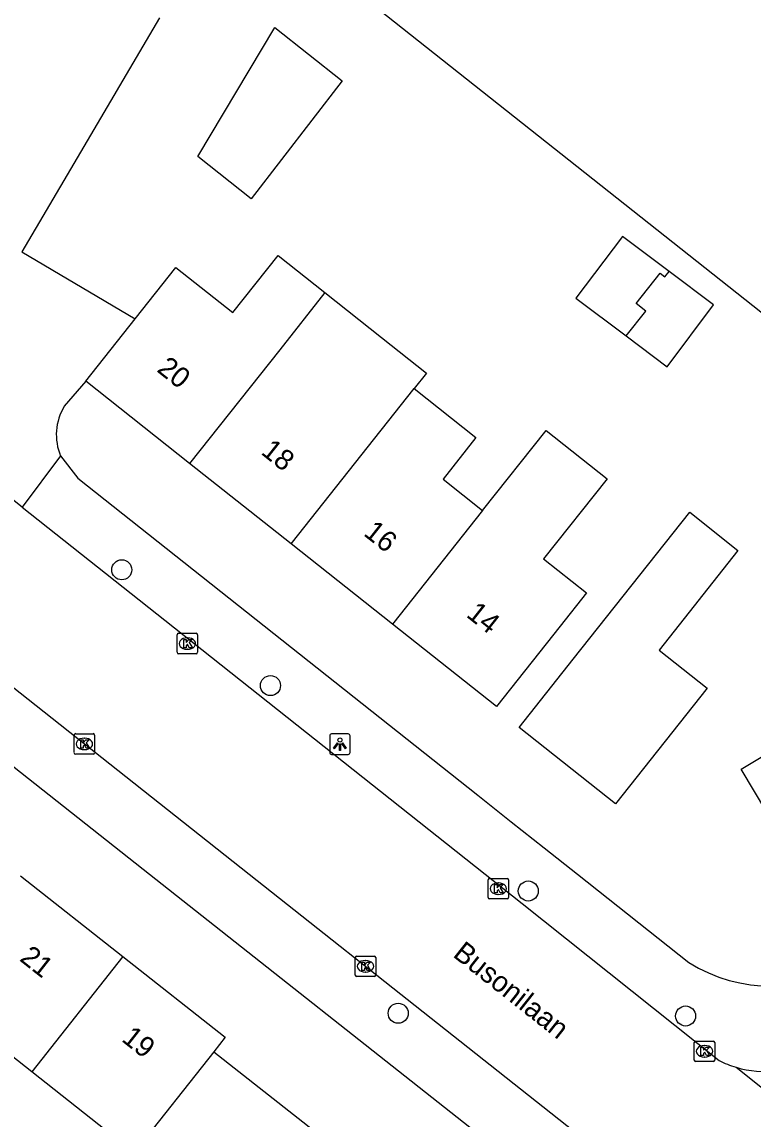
# Model space of a CAD drawing. Extents: x 159222 to 160346, y 381249 to 382166.
# Drawn here: x 160159.7 to 160195.3, y 381988.1 to 382041.6 of the extents above; entities that cross this region are included whole.
import ezdxf

# ---------------------------------------------------------------- set-up
doc = ezdxf.new("R2010")
doc.units = 0
for name, color, linetype in [('IMGEO_Boom', 7, 'Continuous'), ('IMGEO_Kolk', 7, 'Continuous'), ('IMGEO_Lichtpunt', 7, 'Continuous'), ('IMGEO_Muur', 7, 'Continuous'), ('IMGEO_Openbare_ruimte_label', 7, 'Continuous'), ('IMGEO_Pand', 7, 'Continuous'), ('IMGEO_Pand_nummerreeks', 7, 'Continuous'), ('IMGEO_Rijbaan_lokaal_open', 7, 'Continuous'), ('IMGEO_Voetpad_open', 7, 'Continuous')]:
    doc.layers.add(name, color=color, linetype=linetype)

msp = doc.modelspace()

# ---------------------------------------------------------------- linework, layer by layer
at = {"layer": 'IMGEO_Boom'}
for centre in [(160164.533, 382014.84), (160171.786, 382009.194), (160184.362, 381999.177), (160178.018, 381993.215), (160192.036, 381993.082)]:
    msp.add_circle(centre, 0.489, dxfattribs=at)
at = {"layer": 'IMGEO_Kolk'}
for p, q in [((160167.308, 382011.742), (160168.16, 382011.742)), ((160167.233, 382010.816), (160167.233, 382011.668)), ((160167.721, 382011.522), (160167.746, 382011.522)), ((160168.234, 382011.668), (160168.234, 382010.816)), ((160168.16, 382010.742), (160167.308, 382010.742)), ((160167.744, 382010.962), (160167.719, 382010.962)), ((160162.21, 382005.923), (160162.21, 382006.775)), ((160162.285, 382006.849), (160163.137, 382006.849)), ((160162.698, 382006.629), (160162.723, 382006.629)), ((160163.211, 382006.775), (160163.211, 382005.923)), ((160162.721, 382006.069), (160162.696, 382006.069)), ((160163.137, 382005.849), (160162.285, 382005.849)), ((160182.399, 381998.864), (160182.399, 381999.716)), ((160182.474, 381999.79), (160183.326, 381999.79)), ((160182.887, 381999.57), (160182.912, 381999.57)), ((160183.4, 381999.716), (160183.4, 381998.864)), ((160182.91, 381999.01), (160182.885, 381999.01)), ((160183.326, 381998.79), (160182.474, 381998.79)), ((160175.922, 381995.079), (160175.922, 381995.931)), ((160175.997, 381996.005), (160176.849, 381996.005)), ((160176.41, 381995.785), (160176.435, 381995.785)), ((160176.923, 381995.931), (160176.923, 381995.079)), ((160176.433, 381995.225), (160176.408, 381995.225)), ((160176.849, 381995.005), (160175.997, 381995.005)), ((160192.458, 381990.936), (160192.458, 381991.788)), ((160192.533, 381991.862), (160193.385, 381991.862)), ((160192.946, 381991.642), (160192.971, 381991.642)), ((160193.459, 381991.788), (160193.459, 381990.936)), ((160192.969, 381991.082), (160192.944, 381991.082)), ((160193.385, 381990.862), (160192.533, 381990.862))]:
    msp.add_line(p, q, dxfattribs=at)
for points in [[(160167.308, 382011.742), (160168.16, 382011.742)], [(160167.233, 382010.816), (160167.233, 382011.668)], [(160167.554, 382011.442), (160167.677, 382011.442), (160167.677, 382011.291), (160167.807, 382011.442), (160167.971, 382011.442), (160167.825, 382011.291), (160167.978, 382011.042), (160167.826, 382011.042), (160167.741, 382011.206), (160167.677, 382011.139), (160167.677, 382011.042), (160167.554, 382011.042), (160167.554, 382011.442)], [(160168.234, 382011.668), (160168.234, 382010.816)], [(160168.16, 382010.742), (160167.308, 382010.742)], [(160162.21, 382005.923), (160162.21, 382006.775)], [(160162.285, 382006.849), (160163.137, 382006.849)], [(160162.531, 382006.549), (160162.654, 382006.549), (160162.654, 382006.398), (160162.784, 382006.549), (160162.948, 382006.549), (160162.802, 382006.398), (160162.955, 382006.149), (160162.803, 382006.149), (160162.718, 382006.313), (160162.654, 382006.246), (160162.654, 382006.149), (160162.531, 382006.149), (160162.531, 382006.549)], [(160163.211, 382006.775), (160163.211, 382005.923)], [(160163.137, 382005.849), (160162.285, 382005.849)], [(160182.399, 381998.864), (160182.399, 381999.716)], [(160182.474, 381999.79), (160183.326, 381999.79)], [(160182.72, 381999.49), (160182.843, 381999.49), (160182.843, 381999.339), (160182.973, 381999.49), (160183.137, 381999.49), (160182.991, 381999.339), (160183.144, 381999.09), (160182.992, 381999.09), (160182.907, 381999.254), (160182.843, 381999.187), (160182.843, 381999.09), (160182.72, 381999.09), (160182.72, 381999.49)], [(160183.4, 381999.716), (160183.4, 381998.864)], [(160183.326, 381998.79), (160182.474, 381998.79)], [(160175.922, 381995.079), (160175.922, 381995.931)], [(160175.997, 381996.005), (160176.849, 381996.005)], [(160176.243, 381995.705), (160176.366, 381995.705), (160176.366, 381995.554), (160176.496, 381995.705), (160176.66, 381995.705), (160176.514, 381995.554), (160176.667, 381995.305), (160176.515, 381995.305), (160176.43, 381995.469), (160176.366, 381995.402), (160176.366, 381995.305), (160176.243, 381995.305), (160176.243, 381995.705)], [(160176.923, 381995.931), (160176.923, 381995.079)], [(160176.849, 381995.005), (160175.997, 381995.005)], [(160192.458, 381990.936), (160192.458, 381991.788)], [(160192.533, 381991.862), (160193.385, 381991.862)], [(160192.779, 381991.562), (160192.902, 381991.562), (160192.902, 381991.411), (160193.032, 381991.562), (160193.196, 381991.562), (160193.05, 381991.411), (160193.203, 381991.162), (160193.051, 381991.162), (160192.966, 381991.326), (160192.902, 381991.259), (160192.902, 381991.162), (160192.779, 381991.162), (160192.779, 381991.562)], [(160193.459, 381991.788), (160193.459, 381990.936)], [(160193.385, 381990.862), (160192.533, 381990.862)]]:
    msp.add_lwpolyline(points, dxfattribs=at)
for centre, start, end in [((160167.31, 382011.666), 91.552, 178.448), ((160167.31, 382011.666), 91.552, 178.448), ((160168.158, 382011.666), 1.552, 88.448), ((160168.158, 382011.666), 1.552, 88.448), ((160167.31, 382010.818), 181.552, 268.448), ((160167.31, 382010.818), 181.552, 268.448), ((160168.158, 382010.818), 271.552, 358.448), ((160168.158, 382010.818), 271.552, 358.448), ((160162.287, 382006.773), 91.552, 178.448), ((160162.287, 382006.773), 91.552, 178.448), ((160163.135, 382006.773), 1.552, 88.448), ((160163.135, 382006.773), 1.552, 88.448), ((160162.287, 382005.925), 181.552, 268.448), ((160162.287, 382005.925), 181.552, 268.448), ((160163.135, 382005.925), 271.552, 358.448), ((160163.135, 382005.925), 271.552, 358.448), ((160182.476, 381999.714), 91.552, 178.448), ((160182.476, 381999.714), 91.552, 178.448), ((160183.324, 381999.714), 1.552, 88.448), ((160183.324, 381999.714), 1.552, 88.448), ((160182.476, 381998.866), 181.552, 268.448), ((160182.476, 381998.866), 181.552, 268.448), ((160183.324, 381998.866), 271.552, 358.448), ((160183.324, 381998.866), 271.552, 358.448), ((160175.999, 381995.929), 91.552, 178.448), ((160175.999, 381995.929), 91.552, 178.448), ((160176.847, 381995.929), 1.552, 88.448), ((160176.847, 381995.929), 1.552, 88.448), ((160175.999, 381995.081), 181.552, 268.448), ((160175.999, 381995.081), 181.552, 268.448), ((160176.847, 381995.081), 271.552, 358.448), ((160176.847, 381995.081), 271.552, 358.448), ((160192.535, 381991.786), 91.552, 178.448), ((160192.535, 381991.786), 91.552, 178.448), ((160193.383, 381991.786), 1.552, 88.448), ((160193.383, 381991.786), 1.552, 88.448), ((160192.535, 381990.938), 181.552, 268.448), ((160192.535, 381990.938), 181.552, 268.448), ((160193.383, 381990.938), 271.552, 358.448), ((160193.383, 381990.938), 271.552, 358.448)]:
    msp.add_arc(centre, 0.0765, start, end, dxfattribs=at)
for centre, major_axis, ratio, start_param, end_param in [((160167.72, 382011.242), (-0.387, 0.002), 0.722429, 4.712389, 7.853982), ((160167.745, 382011.242), (-0.39, 0.002), 0.717154, 1.570796, 4.712389), ((160162.697, 382006.349), (-0.387, 0.002), 0.722429, 4.712389, 7.853982), ((160162.722, 382006.349), (-0.39, 0.002), 0.717154, 1.570796, 4.712389), ((160182.886, 381999.29), (-0.387, 0.002), 0.722429, 4.712389, 7.853982), ((160182.911, 381999.29), (-0.39, 0.002), 0.717154, 1.570796, 4.712389), ((160176.409, 381995.505), (-0.387, 0.002), 0.722429, 4.712389, 7.853982), ((160176.434, 381995.505), (-0.39, 0.002), 0.717154, 1.570796, 4.712389), ((160192.945, 381991.362), (-0.387, 0.002), 0.722429, 4.712389, 7.853982), ((160192.97, 381991.362), (-0.39, 0.002), 0.717154, 1.570796, 4.712389)]:
    msp.add_ellipse(centre, major_axis=major_axis, ratio=ratio, start_param=start_param, end_param=end_param, dxfattribs=at)
at = {"layer": 'IMGEO_Lichtpunt'}
for p, q in [((160174.675, 382006.741), (160174.675, 382005.934)), ((160174.675, 382006.741), (160174.675, 382005.934)), ((160175.577, 382006.836), (160174.769, 382006.836)), ((160175.577, 382006.836), (160174.769, 382006.836)), ((160175.671, 382005.934), (160175.671, 382006.741)), ((160175.671, 382005.934), (160175.671, 382006.741)), ((160174.769, 382005.84), (160175.577, 382005.84)), ((160174.769, 382005.84), (160175.577, 382005.84))]:
    msp.add_line(p, q, dxfattribs=at)
for points in [[(160175.049, 382006.405), (160175.088, 382006.377), (160174.9, 382006.115), (160174.862, 382006.142), (160175.049, 382006.405)], [(160175.261, 382006.377), (160175.299, 382006.404), (160175.486, 382006.142), (160175.447, 382006.114), (160175.261, 382006.377)], [(160175.151, 382006.357), (160175.198, 382006.357), (160175.198, 382006.035), (160175.151, 382006.035), (160175.151, 382006.357)]]:
    msp.add_lwpolyline(points, dxfattribs=at)
msp.add_circle((160175.174, 382006.539), 0.0994, dxfattribs=at)
for centre, start, end in [((160174.769, 382006.741), 90, 180), ((160174.769, 382006.741), 90, 180), ((160175.577, 382006.741), 0, 90), ((160175.577, 382006.741), 0, 90), ((160174.769, 382005.934), 180, 270), ((160174.769, 382005.934), 180, 270), ((160175.577, 382005.934), 270, 0), ((160175.577, 382005.934), 270, 360)]:
    msp.add_arc(centre, 0.0946, start, end, dxfattribs=at)
at = {"layer": 'IMGEO_Muur'}
msp.add_lwpolyline([(160181.902, 382003.848), (160183.535, 382002.554), (160185.145, 382001.278), (160186.758, 382000), (160192.196, 381995.692)], dxfattribs=at)
at = {"layer": 'IMGEO_Pand'}
for points in [[(160211.313, 382033.447), (160198.054, 382025.542), (160173.539, 382044.963), (160179.55, 382055.171), (160182.923, 382060.898)], [(160166.38, 382041.758), (160162.197, 382034.654), (160159.659, 382030.345)], [(160170.842, 382032.934), (160168.239, 382034.996), (160172.003, 382041.283), (160175.286, 382038.68), (160170.842, 382032.934)], [(160191.238, 382029.381), (160188.95, 382031.1), (160186.688, 382028.089), (160189.14, 382026.246)], [(160165.183, 382027.072), (160167.174, 382029.585), (160169.951, 382027.385), (160172.155, 382030.167), (160174.443, 382028.355)], [(160189.14, 382026.246), (160190.097, 382027.455), (160189.626, 382027.828), (160190.794, 382029.304), (160191.03, 382029.118), (160191.238, 382029.381)], [(160189.14, 382026.246), (160191.141, 382024.742), (160193.403, 382027.755), (160191.238, 382029.381)], [(160174.443, 382028.355), (160172.238, 382025.573), (160167.842, 382020.023)], [(160174.443, 382028.355), (160177.204, 382026.169), (160179.392, 382024.435), (160178.788, 382023.674)], [(160162.777, 382024.035), (160165.183, 382027.072)], [(160167.842, 382020.023), (160162.777, 382024.035)], [(160172.79, 382016.103), (160177.187, 382021.653), (160178.788, 382023.674)], [(160178.788, 382023.674), (160181.806, 382021.284), (160180.205, 382019.262), (160182.135, 382017.733)], [(160182.135, 382017.733), (160185.23, 382021.639), (160188.206, 382019.282), (160185.111, 382015.376), (160187.203, 382013.719), (160185.91, 382012.087), (160182.805, 382008.168), (160177.738, 382012.183)], [(160172.79, 382016.103), (160167.842, 382020.023)], [(160182.135, 382017.733), (160177.738, 382012.183)], [(160194.59, 382015.784), (160190.739, 382010.925), (160193.088, 382009.064), (160188.616, 382003.421), (160183.914, 382007.147), (160186.553, 382010.478), (160192.236, 382017.65), (160194.59, 382015.784)], [(160177.738, 382012.183), (160172.79, 382016.103)], [(160203.81, 382002.51), (160199.595, 382000), (160198.272, 381999.212), (160197.801, 382000), (160194.739, 382005.121), (160199.034, 382007.682), (160200.285, 382008.428)], [(160159.601, 381999.913), (160164.588, 381995.98)], [(160164.588, 381995.98), (160160.15, 381990.354)], [(160164.588, 381995.98), (160169.581, 381992.043), (160169.028, 381991.343)], [(160160.15, 381990.354), (160155.165, 381994.285)], [(160169.028, 381991.343), (160165.135, 381986.422)], [(160169.028, 381991.343), (160174.123, 381987.314)], [(160165.135, 381986.422), (160164.969, 381986.553), (160164.507, 381986.918), (160160.15, 381990.354)]]:
    msp.add_lwpolyline(points, dxfattribs=at)
at = {"layer": 'IMGEO_Rijbaan_lokaal_open'}
for points in [[(160159.669, 382017.89), (160153.216, 382022.998)], [(160159.669, 382017.89), (160166.634, 382012.378), (160184.067, 381998.574), (160193.666, 381990.913)], [(160152.766, 382014.214), (160170.741, 382000), (160222.676, 381958.931)], [(160194.495, 381990.58), (160205.117, 381982.119)]]:
    msp.add_lwpolyline(points, dxfattribs=at)
for centre, radius, start, end in [((160195.857, 381995.168), 4.786, 242.76, 253.4704), ((160195.853, 381995.155), 4.772, 253.4732, 302.4058)]:
    msp.add_arc(centre, radius, start, end, dxfattribs=at)
at = {"layer": 'IMGEO_Voetpad_open'}
for points in [[(160159.659, 382030.345), (160165.183, 382027.072)], [(160162.777, 382024.035), (160161.732, 382022.812)], [(160161.552, 382020.389), (160159.669, 382017.89)], [(160161.552, 382020.389), (160162.394, 382019.303), (160181.902, 382003.848), (160183.535, 382002.554), (160185.145, 382001.278), (160186.758, 382000), (160192.196, 381995.692)], [(160151.974, 382010.99), (160165.891, 382000), (160182.521, 381986.867)]]:
    msp.add_lwpolyline(points, dxfattribs=at)
for centre, radius, start, end in [((160164, 382021.425), 2.659, 148.5615, 202.9414), ((160196.232, 382002.153), 7.618, 238.008, 302.3452)]:
    msp.add_arc(centre, radius, start, end, dxfattribs=at)

# ---------------------------------------------------------------- texts
at = {"layer": 'IMGEO_Openbare_ruimte_label'}
msp.add_text('Busonilaan', height=1, rotation=321.6625, dxfattribs=at).set_placement((160180.637, 381996.01))
at = {"layer": 'IMGEO_Pand_nummerreeks'}
for s, rotation, p in [('20', 321.6118, (160166.199, 382024.539)), ('18', 321.6118, (160171.277, 382020.516)), ('16', 321.6118, (160176.282, 382016.551)), ('14', 321.6123, (160181.29, 382012.583)), ('21', 321.7406, (160159.505, 381995.812)), ('19', 321.7379, (160164.477, 381991.889))]:
    msp.add_text(s, height=1, rotation=rotation, dxfattribs=at).set_placement(p)

doc.saveas('drawing.dxf')
